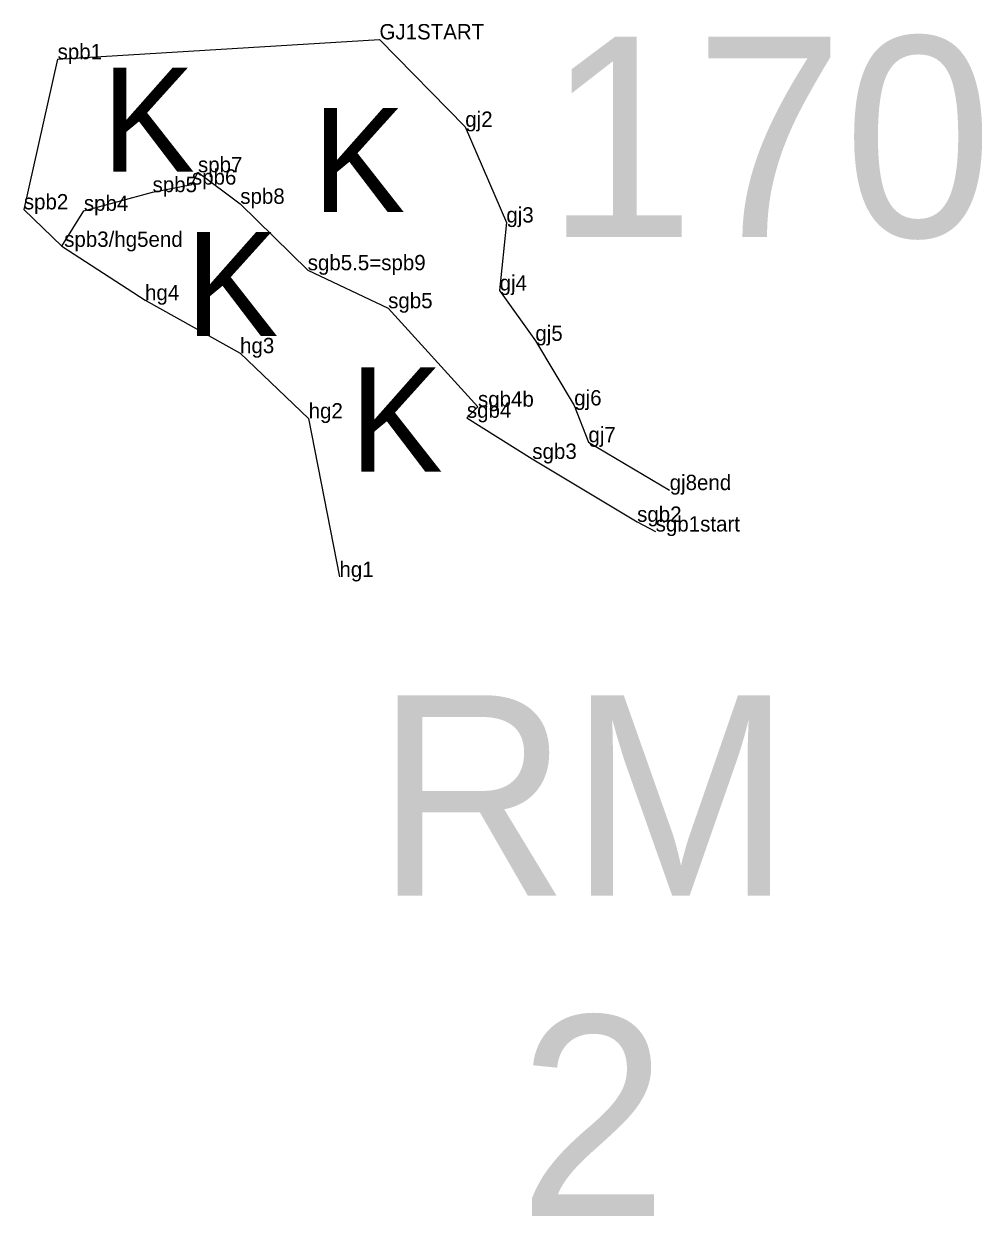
# Model space of a CAD drawing. Extents: x 2072529 to 2268812, y 436423 to 470008.
# Drawn here: x 2195534.8 to 2195847.4, y 452097.2 to 452486.1 of the extents above; entities that cross this region are included whole.
import ezdxf

# ---------------------------------------------------------------- set-up
doc = ezdxf.new("R2010")
doc.units = 0
for name, color, linetype in [('Old_Level_10', 7, 'Continuous'), ('Old_Level_20', 7, 'Continuous'), ('Old_Level_52', 7, 'Continuous'), ('Old_Level_55', 7, 'Continuous'), ('Old_Level_60', 7, 'Continuous'), ('Old_Level_62', 7, 'Continuous')]:
    doc.layers.add(name, color=color, linetype=linetype)

msp = doc.modelspace()

# ---------------------------------------------------------------- linework, layer by layer
at = {"layer": 'Old_Level_10'}
msp.add_lwpolyline([(2195545.807, 452474.523), (2195534.8, 452425.575), (2195547.192, 452413.563), (2195554.384, 452425.097), (2195576.793, 452431.193), (2195589.642, 452433.645), (2195591.608, 452437.672), (2195605.411, 452427.384), (2195627.411, 452405.72), (2195653.645, 452393.338), (2195682.961, 452361.22), (2195679.341, 452357.606), (2195700.686, 452344.185), (2195734.876, 452323.675), (2195740.927, 452320.514)], dxfattribs=at)
at = {"layer": 'Old_Level_20'}
for p, q in [((2195650.818, 452481.008), (2195650.818, 452481.008)), ((2195545.807, 452474.523), (2195545.807, 452474.523)), ((2195678.809, 452452.489), (2195678.809, 452452.489)), ((2195591.608, 452437.672), (2195591.608, 452437.672)), ((2195589.642, 452433.645), (2195589.642, 452433.645)), ((2195576.793, 452431.193), (2195576.793, 452431.193)), ((2195534.8, 452425.575), (2195534.8, 452425.575)), ((2195554.384, 452425.097), (2195554.384, 452425.097)), ((2195605.411, 452427.384), (2195605.411, 452427.384)), ((2195692.216, 452421.276), (2195692.216, 452421.276)), ((2195547.192, 452413.563), (2195547.192, 452413.563)), ((2195547.192, 452413.563), (2195547.192, 452413.563)), ((2195627.411, 452405.72), (2195627.411, 452405.72)), ((2195690.015, 452399.111), (2195690.015, 452399.111)), ((2195574.339, 452395.963), (2195574.339, 452395.963)), ((2195653.645, 452393.338), (2195653.645, 452393.338)), ((2195701.677, 452382.682), (2195701.677, 452382.682)), ((2195605.346, 452378.676), (2195605.346, 452378.676)), ((2195714.365, 452361.636), (2195714.365, 452361.636)), ((2195682.961, 452361.22), (2195682.961, 452361.22)), ((2195627.722, 452357.388), (2195627.722, 452357.388)), ((2195679.341, 452357.606), (2195679.341, 452357.606)), ((2195719.001, 452349.614), (2195719.001, 452349.614)), ((2195700.686, 452344.185), (2195700.686, 452344.185)), ((2195745.495, 452334.021), (2195745.495, 452334.021)), ((2195734.876, 452323.675), (2195734.876, 452323.675)), ((2195740.927, 452320.514), (2195740.927, 452320.514)), ((2195637.759, 452305.703), (2195637.759, 452305.703))]:
    msp.add_line(p, q, dxfattribs=at)
at = {"layer": 'Old_Level_52'}
for points in [[(2195545.807, 452474.523), (2195650.818, 452481.008), (2195678.809, 452452.489), (2195692.216, 452421.276), (2195690.015, 452399.111), (2195701.677, 452382.682), (2195714.365, 452361.636), (2195719.001, 452349.614), (2195745.495, 452334.021)], [(2195547.192, 452413.563), (2195574.339, 452395.963), (2195605.346, 452378.676), (2195627.722, 452357.388), (2195637.759, 452305.703)]]:
    msp.add_lwpolyline(points, dxfattribs=at)

# ---------------------------------------------------------------- texts
at = {"layer": 'Old_Level_55'}
for p in [(2195560.317, 452437.838), (2195628.952, 452424.675), (2195587.583, 452384.246), (2195641.174, 452340.057)]:
    msp.add_text('K', height=34, dxfattribs=at).set_placement(p)
at = {"layer": 'Old_Level_60'}
for s, p in [('GJ1START', (2195650.818, 452481.008)), ('spb1', (2195545.807, 452474.523)), ('gj2', (2195678.809, 452452.489)), ('spb7', (2195591.608, 452437.672)), ('spb5', (2195576.793, 452431.193)), ('spb6', (2195589.642, 452433.645)), ('spb8', (2195605.411, 452427.384)), ('spb2', (2195534.8, 452425.575)), ('spb4', (2195554.384, 452425.097)), ('gj3', (2195692.216, 452421.276)), ('spb3/hg5end', (2195547.958, 452413.355)), ('spb3', (2195547.958, 452413.355)), ('sgb5.5=spb9', (2195627.411, 452405.72)), ('gj4', (2195690.015, 452399.111)), ('hg4', (2195574.339, 452395.963)), ('sgb5', (2195653.645, 452393.338)), ('gj5', (2195701.677, 452382.682)), ('hg3', (2195605.346, 452378.676)), ('sgb4b', (2195682.961, 452361.22)), ('gj6', (2195714.365, 452361.636)), ('hg2', (2195627.722, 452357.388)), ('sgb4', (2195679.341, 452357.606)), ('gj7', (2195719.001, 452349.614)), ('sgb3', (2195700.686, 452344.185)), ('gj8end', (2195745.495, 452334.021)), ('sgb2', (2195734.876, 452323.675)), ('sgb1start', (2195740.927, 452320.514)), ('hg1', (2195637.759, 452305.703))]:
    msp.add_text(s, height=5, dxfattribs=at).set_placement(p)
at = {"layer": 'Old_Level_62'}
for s, p in [('170', (2195705.077, 452416.56)), ('RM', (2195649.543, 452201.786)), ('2', (2195696.19, 452097.242))]:
    msp.add_text(s, height=65.34, dxfattribs=at).set_placement(p)

doc.saveas('drawing.dxf')
